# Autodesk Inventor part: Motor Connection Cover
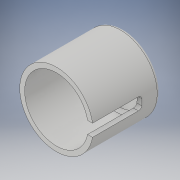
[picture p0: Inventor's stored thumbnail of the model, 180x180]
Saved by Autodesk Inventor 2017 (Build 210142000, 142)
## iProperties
Created: 2017-05
Part Number: Motor Connection Cover
Material: Generic
Document SubType Name: Modeling
Designer: Stan
Density: 1 g/cm^3
Appearance: Default
Author: Stan
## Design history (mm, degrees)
sketch "Sketch1"
  geometry: C1 r 16.51 at (0, 0); C2 r 19.05 at (0, 0); 1 further point
  constraints: 2 centre point, 2 coincident
  dimensions: "d0" = 33.02 diameter of C1; "d1" = 38.1 diameter of C2
extrude "Extrusion1" new body sketch "Sketch1" distance "d2" = 34.925; taper "d3" = 0 deg
sketch "Sketch2"
  geometry: C1 r 16.51 at (0, 0); 1 further point
  constraints: 1 centre point, 1 coincident
extrude "Extrusion2" join sketch "Sketch2" distance "d4" = 2.54; taper "d5" = 0 deg
fillet "Fillet1" dims "d6" = 1.5875
sketch "Sketch3"
  geometry: L1 (18.784, 3.175)-(16.202, 3.175); L2 (16.202, -3.175)-(18.784, -3.175); A1 r 16.51 centre (0, 0) between (16.202, -3.175) and (16.202, 3.175); A2 r 19.05 centre (0, 0) between (18.784, -3.175) and (18.784, 3.175); 1 further point
  constraints: 4 end point, 4 point on circle, 2 centre point, 2 coincident, 2 horizontal
  dimensions: "d7" = 3.175 distance from line of L1 point (0, 0); "d8" = 3.175 distance from line of L2 point (0, 0)
extrude "Extrusion3" cut sketch "Sketch3" distance "d9" = 25.4; taper "d10" = 0 deg
fillet "Fillet2" dims "d11" = 1.5875
fillet "Fillet3" dims "d12" = 1.5875
body "Solid1"
